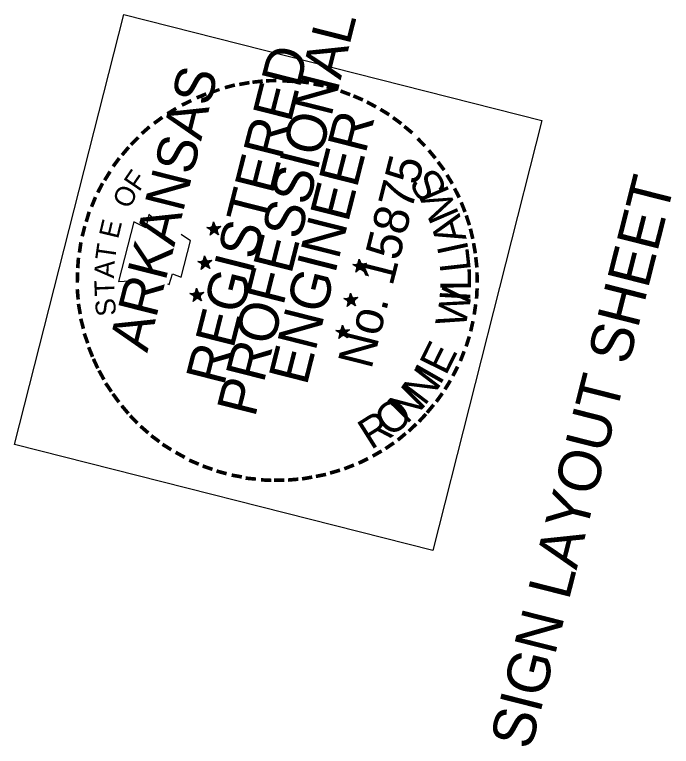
# Model space of a CAD drawing. Extents: x 670257 to 671518, y 737783 to 738188.
# Drawn here: x 670784.83 to 670793.09, y 738048.64 to 738057.85 of the extents above; entities that cross this region are included whole.
import ezdxf

# ---------------------------------------------------------------- set-up
doc = ezdxf.new("R2010")
doc.units = 0
for name, color, linetype in [('R_Border Notes', 7, 'Continuous'), ('R_Border PE', 7, 'Continuous'), ('R_Border Prem', 7, 'Continuous')]:
    doc.layers.add(name, color=color, linetype=linetype)

msp = doc.modelspace()

# ---------------------------------------------------------------- linework, layer by layer
at = {"layer": 'R_Border PE'}
for p, q in [((670787.3344, 738055.24), (670787.3202, 738055.1637)), ((670787.3344, 738055.24), (670787.3287, 738055.1667)), ((670787.3344, 738055.24), (670787.3335, 738055.1654)), ((670787.3344, 738055.24), (670787.3395, 738055.1484)), ((670787.3344, 738055.24), (670787.3427, 738055.1812)), ((670787.3344, 738055.24), (670787.3457, 738055.183)), ((670787.3344, 738055.24), (670787.3494, 738055.1872)), ((670787.2523, 738055.1706), (670787.3172, 738055.1722)), ((670787.3395, 738055.1484), (670787.2523, 738055.1706)), ((670787.2523, 738055.1706), (670787.3159, 738055.1673)), ((670787.2523, 738055.1706), (670787.3117, 738055.1607)), ((670787.2523, 738055.1706), (670787.3116, 738055.1504)), ((670787.2523, 738055.1706), (670787.3104, 738055.1455)), ((670787.2523, 738055.1706), (670787.3068, 738055.1413)), ((670787.2914, 738055.0704), (670787.3395, 738055.1484)), ((670787.4251, 738055.1809), (670787.3395, 738055.1484)), ((670787.3987, 738055.0767), (670787.3395, 738055.1484)), ((670787.4251, 738055.1809), (670787.3469, 738055.1672)), ((670787.4251, 738055.1809), (670787.3481, 738055.1721)), ((670787.4251, 738055.1809), (670787.3559, 738055.1623)), ((670787.4251, 738055.1809), (670787.3589, 738055.1435)), ((670787.4251, 738055.1809), (670787.3638, 738055.1526)), ((670787.4251, 738055.1809), (670787.3662, 738055.1417)), ((670787.2914, 738055.0704), (670787.3146, 738055.1316)), ((670787.2914, 738055.0704), (670787.3188, 738055.1279)), ((670787.2914, 738055.0704), (670787.3213, 738055.1273)), ((670787.2914, 738055.0704), (670787.3303, 738055.1224)), ((670787.2914, 738055.0704), (670787.3352, 738055.1212)), ((670787.2914, 738055.0704), (670787.34, 738055.1199)), ((670787.3987, 738055.0767), (670787.3382, 738055.123)), ((670787.3987, 738055.0767), (670787.3461, 738055.1236)), ((670787.3987, 738055.0767), (670787.3498, 738055.1278)), ((670787.3987, 738055.0767), (670787.3589, 738055.1435)), ((670787.3987, 738055.0767), (670787.3589, 738055.1332)), ((670787.3987, 738055.0767), (670787.3668, 738055.1441)), ((670787.2232, 738054.8117), (670787.209, 738054.7354)), ((670787.2232, 738054.8117), (670787.2175, 738054.7384)), ((670787.2232, 738054.8117), (670787.2223, 738054.7371)), ((670787.2232, 738054.8117), (670787.2283, 738054.7201)), ((670787.2232, 738054.8117), (670787.2315, 738054.7529)), ((670787.2232, 738054.8117), (670787.2351, 738054.7571)), ((670787.2232, 738054.8117), (670787.2382, 738054.7589)), ((670787.1387, 738054.7429), (670787.206, 738054.7439)), ((670787.2283, 738054.7201), (670787.1387, 738054.7429)), ((670787.1387, 738054.7429), (670787.2023, 738054.7396)), ((670787.1387, 738054.7429), (670787.2005, 738054.7324)), ((670787.1387, 738054.7429), (670787.198, 738054.7227)), ((670787.1387, 738054.7429), (670787.1992, 738054.7172)), ((670787.1387, 738054.7429), (670787.1962, 738054.7154)), ((670787.1802, 738054.6421), (670787.2283, 738054.7201)), ((670787.1802, 738054.6421), (670787.201, 738054.7039)), ((670787.1802, 738054.6421), (670787.2058, 738054.7026)), ((670787.1802, 738054.6421), (670787.2101, 738054.699)), ((670787.1802, 738054.6421), (670787.2191, 738054.6941)), ((670787.1802, 738054.6421), (670787.224, 738054.6929)), ((670787.1802, 738054.6421), (670787.2288, 738054.6916)), ((670787.2881, 738054.6508), (670787.227, 738054.6947)), ((670787.3145, 738054.755), (670787.2283, 738054.7201)), ((670787.2881, 738054.6508), (670787.2283, 738054.7201)), ((670787.3145, 738054.755), (670787.2345, 738054.7444)), ((670787.2881, 738054.6508), (670787.2349, 738054.6953)), ((670787.3145, 738054.755), (670787.2357, 738054.7389)), ((670787.2881, 738054.6508), (670787.2386, 738054.6995)), ((670787.3145, 738054.755), (670787.2447, 738054.734)), ((670787.3145, 738054.755), (670787.2477, 738054.7152)), ((670787.2881, 738054.6508), (670787.2477, 738054.7152)), ((670787.2881, 738054.6508), (670787.2477, 738054.7049)), ((670787.3145, 738054.755), (670787.2526, 738054.7243)), ((670787.3145, 738054.755), (670787.255, 738054.7134)), ((670787.2881, 738054.6508), (670787.2556, 738054.7158)), ((670789.1739, 738054.6832), (670789.0867, 738054.7053)), ((670789.0867, 738054.7053), (670789.151, 738054.7045)), ((670789.0867, 738054.7053), (670789.1504, 738054.7021)), ((670789.0867, 738054.7053), (670789.1485, 738054.6948)), ((670789.0867, 738054.7053), (670789.1461, 738054.6851)), ((670789.0867, 738054.7053), (670789.1448, 738054.6803)), ((670789.0867, 738054.7053), (670789.1436, 738054.6754)), ((670789.1682, 738054.7723), (670789.1546, 738054.6984)), ((670789.1682, 738054.7723), (670789.1631, 738054.7014)), ((670789.1682, 738054.7723), (670789.1679, 738054.7002)), ((670789.1682, 738054.7723), (670789.1739, 738054.6832)), ((670789.1682, 738054.7723), (670789.1765, 738054.7135)), ((670789.1682, 738054.7723), (670789.1826, 738054.7171)), ((670789.1682, 738054.7723), (670789.1856, 738054.7189)), ((670789.2596, 738054.7156), (670789.1739, 738054.6832)), ((670789.2596, 738054.7156), (670789.1807, 738054.6995)), ((670789.2596, 738054.7156), (670789.1819, 738054.7044)), ((670789.2596, 738054.7156), (670789.1922, 738054.694)), ((670789.2596, 738054.7156), (670789.1951, 738054.6752)), ((670789.2596, 738054.7156), (670789.1976, 738054.6849)), ((670789.2596, 738054.7156), (670789.2024, 738054.6734)), ((670789.1258, 738054.6051), (670789.1739, 738054.6832)), ((670789.1258, 738054.6051), (670789.1484, 738054.6639)), ((670789.1258, 738054.6051), (670789.1533, 738054.6627)), ((670789.1258, 738054.6051), (670789.1575, 738054.659)), ((670789.1258, 738054.6051), (670789.1648, 738054.6572)), ((670789.1258, 738054.6051), (670789.1714, 738054.6529)), ((670789.1258, 738054.6051), (670789.1763, 738054.6517)), ((670789.2331, 738054.6114), (670789.172, 738054.6553)), ((670789.2331, 738054.6114), (670789.1739, 738054.6832)), ((670789.2331, 738054.6114), (670789.1823, 738054.6553)), ((670789.2331, 738054.6114), (670789.1866, 738054.6619)), ((670789.2331, 738054.6114), (670789.1933, 738054.668)), ((670789.2331, 738054.6114), (670789.1951, 738054.6752)), ((670789.2331, 738054.6114), (670789.2006, 738054.6764)), ((670787.036, 738054.3382), (670787.1033, 738054.3392)), ((670787.1257, 738054.3155), (670787.036, 738054.3382)), ((670787.036, 738054.3382), (670787.0997, 738054.3349)), ((670787.036, 738054.3382), (670787.0984, 738054.3301)), ((670787.036, 738054.3382), (670787.096, 738054.3204)), ((670787.036, 738054.3382), (670787.0966, 738054.3125)), ((670787.036, 738054.3382), (670787.0935, 738054.3107)), ((670787.1205, 738054.407), (670787.1063, 738054.3307)), ((670787.1205, 738054.407), (670787.1148, 738054.3337)), ((670787.1205, 738054.407), (670787.1197, 738054.3325)), ((670787.1205, 738054.407), (670787.1257, 738054.3155)), ((670787.1205, 738054.407), (670787.1288, 738054.3482)), ((670787.1205, 738054.407), (670787.1325, 738054.3524)), ((670787.1205, 738054.407), (670787.1355, 738054.3542)), ((670787.2119, 738054.3503), (670787.1257, 738054.3155)), ((670787.2119, 738054.3503), (670787.1318, 738054.3397)), ((670787.2119, 738054.3503), (670787.133, 738054.3342)), ((670787.2119, 738054.3503), (670787.1421, 738054.3293)), ((670787.2119, 738054.3503), (670787.1451, 738054.3105)), ((670787.2119, 738054.3503), (670787.1499, 738054.3196)), ((670787.2119, 738054.3503), (670787.1523, 738054.3087)), ((670789.057, 738054.344), (670789.0434, 738054.2701)), ((670789.057, 738054.344), (670789.0519, 738054.2731)), ((670789.057, 738054.344), (670789.0567, 738054.2719)), ((670789.057, 738054.344), (670789.0627, 738054.2549)), ((670789.057, 738054.344), (670789.0653, 738054.2852)), ((670789.057, 738054.344), (670789.0689, 738054.2894)), ((670789.057, 738054.344), (670789.075, 738054.2931)), ((670787.0775, 738054.2374), (670787.1257, 738054.3155)), ((670787.0775, 738054.2374), (670787.0983, 738054.2992)), ((670787.0775, 738054.2374), (670787.1032, 738054.2979)), ((670787.0775, 738054.2374), (670787.1074, 738054.2943)), ((670787.0775, 738054.2374), (670787.1171, 738054.2918)), ((670787.0775, 738054.2374), (670787.1213, 738054.2882)), ((670787.0775, 738054.2374), (670787.1262, 738054.287)), ((670787.1855, 738054.2461), (670787.1244, 738054.29)), ((670787.1855, 738054.2461), (670787.1257, 738054.3155)), ((670787.1855, 738054.2461), (670787.1323, 738054.2906)), ((670787.1855, 738054.2461), (670787.1359, 738054.2948)), ((670787.1855, 738054.2461), (670787.145, 738054.3002)), ((670787.1855, 738054.2461), (670787.1451, 738054.3105)), ((670787.1855, 738054.2461), (670787.153, 738054.3111)), ((670789.0627, 738054.2549), (670788.9755, 738054.277)), ((670788.9755, 738054.277), (670789.0398, 738054.2762)), ((670788.9755, 738054.277), (670789.0392, 738054.2738)), ((670788.9755, 738054.277), (670789.0373, 738054.2665)), ((670788.9755, 738054.277), (670789.0349, 738054.2568)), ((670788.9755, 738054.277), (670789.0336, 738054.252)), ((670788.9755, 738054.277), (670789.03, 738054.2477)), ((670789.0146, 738054.1768), (670789.0627, 738054.2549)), ((670789.0146, 738054.1768), (670789.0372, 738054.2356)), ((670789.0146, 738054.1768), (670789.0421, 738054.2343)), ((670789.0146, 738054.1768), (670789.0445, 738054.2337)), ((670789.0146, 738054.1768), (670789.0536, 738054.2289)), ((670789.0146, 738054.1768), (670789.0584, 738054.2276)), ((670789.0146, 738054.1768), (670789.0632, 738054.2264)), ((670789.1219, 738054.1831), (670789.0614, 738054.2294)), ((670789.1483, 738054.2873), (670789.0627, 738054.2549)), ((670789.1219, 738054.1831), (670789.0627, 738054.2549)), ((670789.1483, 738054.2873), (670789.0695, 738054.2712)), ((670789.1483, 738054.2873), (670789.0713, 738054.2785)), ((670789.1219, 738054.1831), (670789.0717, 738054.2294)), ((670789.1219, 738054.1831), (670789.0754, 738054.2336)), ((670789.1483, 738054.2873), (670789.0792, 738054.2688)), ((670789.1219, 738054.1831), (670789.0821, 738054.25)), ((670789.1219, 738054.1831), (670789.0821, 738054.2397)), ((670789.1483, 738054.2873), (670789.0845, 738054.2494)), ((670789.1483, 738054.2873), (670789.0864, 738054.2566)), ((670789.1483, 738054.2873), (670789.0888, 738054.2457)), ((670789.1219, 738054.1831), (670789.0894, 738054.2481)), ((670788.8729, 738053.8723), (670788.9377, 738053.8739)), ((670788.9601, 738053.8502), (670788.8729, 738053.8723)), ((670788.8729, 738053.8723), (670788.9365, 738053.8691)), ((670788.8729, 738053.8723), (670788.9347, 738053.8618)), ((670788.8729, 738053.8723), (670788.9322, 738053.8521)), ((670788.8729, 738053.8723), (670788.931, 738053.8473)), ((670788.8729, 738053.8723), (670788.9273, 738053.843)), ((670788.955, 738053.9418), (670788.9407, 738053.8654)), ((670788.955, 738053.9418), (670788.9492, 738053.8684)), ((670788.955, 738053.9418), (670788.9541, 738053.8672)), ((670788.955, 738053.9418), (670788.9601, 738053.8502)), ((670788.955, 738053.9418), (670788.9626, 738053.8805)), ((670788.955, 738053.9418), (670788.9663, 738053.8847)), ((670788.955, 738053.9418), (670788.9724, 738053.8884)), ((670789.0457, 738053.8827), (670788.9601, 738053.8502)), ((670789.0457, 738053.8827), (670788.9668, 738053.8666)), ((670789.0457, 738053.8827), (670788.9687, 738053.8738)), ((670789.0457, 738053.8827), (670788.9765, 738053.8641)), ((670789.0457, 738053.8827), (670788.9819, 738053.8447)), ((670789.0457, 738053.8827), (670788.9838, 738053.8519)), ((670789.0457, 738053.8827), (670788.9861, 738053.841)), ((670788.9119, 738053.7722), (670788.9601, 738053.8502)), ((670788.9119, 738053.7722), (670788.9352, 738053.8333)), ((670788.9119, 738053.7722), (670788.9394, 738053.8297)), ((670788.9119, 738053.7722), (670788.9418, 738053.829)), ((670788.9119, 738053.7722), (670788.9509, 738053.8242)), ((670788.9119, 738053.7722), (670788.9558, 738053.8229)), ((670788.9119, 738053.7722), (670788.9606, 738053.8217)), ((670789.0193, 738053.7785), (670788.9588, 738053.8247)), ((670789.0193, 738053.7785), (670788.9601, 738053.8502)), ((670789.0193, 738053.7785), (670788.9691, 738053.8247)), ((670789.0193, 738053.7785), (670788.9728, 738053.8289)), ((670789.0193, 738053.7785), (670788.9795, 738053.8453)), ((670789.0193, 738053.7785), (670788.9795, 738053.835)), ((670789.0193, 738053.7785), (670788.9868, 738053.8434))]:
    msp.add_line(p, q, dxfattribs=at)
for points in [[(670786.579, 738055.282), (670786.5198, 738055.3331), (670786.4822, 738055.1647), (670786.3315, 738055.2416), (670786.1404, 738054.488)], [(670787.2523, 738055.1706), (670787.4251, 738055.1809), (670787.2914, 738055.0704), (670787.3344, 738055.24), (670787.3987, 738055.0767), (670787.2523, 738055.1706)], [(670786.7569, 738054.458), (670786.7787, 738054.4525), (670786.818, 738054.5869), (670786.9288, 738054.5459), (670787.0437, 738054.9991), (670786.9276, 738055.0801)], [(670787.1387, 738054.7429), (670787.3145, 738054.755), (670787.1802, 738054.6421), (670787.2232, 738054.8117), (670787.2881, 738054.6508), (670787.1387, 738054.7429)], [(670789.0867, 738054.7053), (670789.2596, 738054.7156), (670789.1258, 738054.6051), (670789.1682, 738054.7723), (670789.2331, 738054.6114), (670789.0867, 738054.7053)], [(670786.1404, 738054.488), (670786.3575, 738054.5)], [(670787.036, 738054.3382), (670787.2119, 738054.3503), (670787.0775, 738054.2374), (670787.1205, 738054.407), (670787.1855, 738054.2461), (670787.036, 738054.3382)], [(670788.9755, 738054.277), (670789.1483, 738054.2873), (670789.0146, 738054.1768), (670789.057, 738054.344), (670789.1219, 738054.1831), (670788.9755, 738054.277)], [(670788.8729, 738053.8723), (670789.0457, 738053.8827), (670788.9119, 738053.7722), (670788.955, 738053.9418), (670789.0193, 738053.7785), (670788.8729, 738053.8723)]]:
    msp.add_lwpolyline(points, dxfattribs=at)
for centre, radius in [((670787.3401, 738055.1481), 0.0431), ((670787.3401, 738055.1481), 0.039), ((670787.3401, 738055.1481), 0.0361), ((670787.3401, 738055.1481), 0.0332), ((670787.3401, 738055.1481), 0.0289), ((670787.3401, 738055.1481), 0.0269), ((670787.3401, 738055.1481), 0.0248), ((670787.3401, 738055.1481), 0.0213), ((670787.3401, 738055.1481), 0.0187), ((670787.3401, 738055.1481), 0.0155), ((670787.3401, 738055.1481), 0.0124), ((670787.3401, 738055.1481), 0.00924), ((670787.3401, 738055.1481), 0.00741), ((670787.3401, 738055.1481), 0.0036), ((670787.2286, 738054.7206), 0.0431), ((670787.2286, 738054.7206), 0.039), ((670787.2286, 738054.7206), 0.0361), ((670787.2286, 738054.7206), 0.0332), ((670787.2286, 738054.7206), 0.0289), ((670787.2286, 738054.7206), 0.0269), ((670787.2286, 738054.7206), 0.0248), ((670787.2286, 738054.7206), 0.0213), ((670787.2286, 738054.7206), 0.0187), ((670787.2286, 738054.7206), 0.0155), ((670787.2286, 738054.7206), 0.0124), ((670787.2286, 738054.7206), 0.00924), ((670787.2286, 738054.7206), 0.00741), ((670787.2286, 738054.7206), 0.0036), ((670789.175, 738054.6817), 0.0431), ((670789.175, 738054.6817), 0.039), ((670789.175, 738054.6817), 0.0361), ((670789.175, 738054.6817), 0.0332), ((670789.175, 738054.6817), 0.0289), ((670789.175, 738054.6817), 0.0269), ((670789.175, 738054.6817), 0.0248), ((670789.175, 738054.6817), 0.0213), ((670789.175, 738054.6817), 0.0187), ((670789.175, 738054.6817), 0.0155), ((670789.175, 738054.6817), 0.0124), ((670789.175, 738054.6817), 0.00924), ((670789.175, 738054.6817), 0.00741), ((670789.175, 738054.6817), 0.0036), ((670787.1261, 738054.3161), 0.0431), ((670787.1261, 738054.3161), 0.039), ((670787.1261, 738054.3161), 0.0361), ((670787.1261, 738054.3161), 0.0332), ((670787.1261, 738054.3161), 0.0289), ((670787.1261, 738054.3161), 0.0269), ((670787.1261, 738054.3161), 0.0248), ((670787.1261, 738054.3161), 0.0213), ((670787.1261, 738054.3161), 0.0187), ((670787.1261, 738054.3161), 0.0155), ((670787.1261, 738054.3161), 0.0124), ((670787.1261, 738054.3161), 0.00924), ((670787.1261, 738054.3161), 0.00741), ((670787.1261, 738054.3161), 0.0036), ((670789.0635, 738054.2542), 0.0431), ((670789.0635, 738054.2542), 0.039), ((670789.0635, 738054.2542), 0.0361), ((670789.0635, 738054.2542), 0.0332), ((670789.0635, 738054.2542), 0.0289), ((670789.0635, 738054.2542), 0.0269), ((670789.0635, 738054.2542), 0.0248), ((670789.0635, 738054.2542), 0.0213), ((670789.0635, 738054.2542), 0.0187), ((670789.0635, 738054.2542), 0.0155), ((670789.0635, 738054.2542), 0.0124), ((670789.0635, 738054.2542), 0.00924), ((670789.0635, 738054.2542), 0.00741), ((670789.0635, 738054.2542), 0.0036), ((670788.961, 738053.8497), 0.0431), ((670788.961, 738053.8497), 0.039), ((670788.961, 738053.8497), 0.0361), ((670788.961, 738053.8497), 0.0332), ((670788.961, 738053.8497), 0.0289), ((670788.961, 738053.8497), 0.0269), ((670788.961, 738053.8497), 0.0248), ((670788.961, 738053.8497), 0.0213), ((670788.961, 738053.8497), 0.0187), ((670788.961, 738053.8497), 0.0155), ((670788.961, 738053.8497), 0.0124), ((670788.961, 738053.8497), 0.00924), ((670788.961, 738053.8497), 0.00741), ((670788.961, 738053.8497), 0.0036)]:
    msp.add_circle(centre, radius, dxfattribs=at)
at = {"layer": 'R_Border Prem'}
msp.add_lwpolyline([(670784.8346, 738052.4383), (670786.2064, 738057.8471), (670791.4647, 738056.5134), (670790.0929, 738051.1047)], close=True, dxfattribs=at)

# ---------------------------------------------------------------- texts
at = {"layer": 'R_Border Notes'}
msp.add_text('SIGN LAYOUT SHEET', height=0.533593, rotation=75.76855, dxfattribs=at).set_placement((670791.3239, 738048.583))
at = {"layer": 'R_Border PE'}
for s, height, rotation, p in [('PROFESSIONAL', 0.499995, 75.76855, (670787.8553, 738052.7686)), ('REGISTERED', 0.5, 75.76855, (670787.4656, 738053.1641)), ('ARKANSAS', 0.5, 75.76855, (670786.5017, 738053.5839)), ('-', 0.3999, 10.43135, (670787.6635, 738056.8124)), ('-', 0.3999, 6.34138, (670787.8176, 738056.8403)), ('-', 0.4, 0.89181, (670787.9723, 738056.8604)), ('-', 0.4, 356.31789, (670788.1664, 738056.8628)), ('-', 0.4, 352.36471, (670788.361, 738056.8573)), ('-', 0.4, 350.09866, (670788.5416, 738056.827)), ('-', 0.35, 19.44384, (670787.3286, 738056.7323)), ('-', 0.4, 15.4369, (670787.496, 738056.7723)), ('-', 0.3999, 345.70922, (670788.6961, 738056.7955)), ('-', 0.3999, 339.28575, (670788.8548, 738056.7501)), ('-', 0.3999, 22.42073, (670787.1603, 738056.6485)), ('-', 0.4, 336.76384, (670789.0104, 738056.6926)), ('-', 0.3999, 25.64828, (670786.983, 738056.5594)), ('-', 0.3999, 331.53115, (670789.1684, 738056.6241)), ('-', 0.4, 31.34714, (670786.8146, 738056.4551)), ('-', 0.4, 328.63664, (670789.3318, 738056.5362)), ('-', 0.4, 36.29826, (670786.659, 738056.3398)), ('ENGINEER', 0.5, 75.76855, (670788.5061, 738053.1684)), ('-', 0.4, 323.65722, (670789.4807, 738056.4418)), ('-', 0.3999, 41.63121, (670786.5173, 738056.2184)), ('-', 0.4, 320.38827, (670789.6168, 738056.3376)), ('-', 0.3999, 45.40945, (670786.3908, 738056.0854)), ('-', 0.4, 314.8398, (670789.7745, 738056.197)), ('-', 0.4, 49.88964, (670786.2873, 738055.9621)), ('No. 15875', 0.44, 75.76855, (670789.3191, 738053.3744)), ('-', 0.4, 309.61379, (670789.9075, 738056.0601)), ('-', 0.4, 53.62364, (670786.1831, 738055.826)), ('-', 0.4, 307.02232, (670790.0192, 738055.9209)), ('-', 0.4, 58.10475, (670786.0843, 738055.6602)), ('F', 0.2499, 55.83921, (670786.3988, 738055.6088)), ('S', 0.3849, 121.46196, (670790.2882, 738055.6493)), ('-', 0.3999, 301.53388, (670790.1254, 738055.7702)), ('-', 0.4, 62.97344, (670786.0068, 738055.5174)), ('O', 0.2499, 66.22005, (670786.2847, 738055.3928)), ('M', 0.3849, 113.32556, (670790.4291, 738055.3335)), ('-', 0.3999, 296.85364, (670790.217, 738055.6128)), ('-', 0.4, 67.93028, (670785.9359, 738055.3497)), ('-', 0.3999, 291.50488, (670790.2971, 738055.4506)), ('-', 0.4, 73.51159, (670785.8759, 738055.1741)), ('A', 0.3849, 105.76014, (670790.5188, 738055.0246)), ('E', 0.25, 76.60089, (670786.1349, 738055.0155)), ('-', 0.4, 288.01764, (670790.3584, 738055.2958)), ('-', 0.3999, 75.95478, (670785.8286, 738054.9978)), ('-', 0.4, 283.12539, (670790.4094, 738055.141)), ('-', 0.3999, 81.66537, (670785.7983, 738054.8069)), ('T', 0.25, 81.79131, (670786.0939, 738054.7422)), ('I', 0.3849, 102.33428, (670790.5458, 738054.8814)), ('-', 0.3999, 280.02017, (670790.4482, 738054.9687)), ('L', 0.3849, 96.33904, (670790.5724, 738054.6279)), ('-', 0.4, 85.9879, (670785.78, 738054.6232)), ('-', 0.4, 276.48697, (670790.4756, 738054.8019)), ('A', 0.25, 86.98173, (670786.0829, 738054.5258)), ('-', 0.3999, 89.3987, (670785.777, 738054.4486)), ('L', 0.3849, 90.3438, (670790.5724, 738054.3729)), ('-', 0.3999, 271.24284, (670790.4925, 738054.6247)), ('T', 0.2499, 92.17215, (670786.0925, 738054.3093)), ('W', 0.3849, 78.78155, (670790.4973, 738053.8877)), ('-', 0.3999, 94.94463, (670785.7891, 738054.2521)), ('I', 0.3849, 86.91795, (670790.5604, 738054.2277)), ('-', 0.4, 267.05431, (670790.4961, 738054.4355)), ('S', 0.2499, 97.36257, (670786.1165, 738054.0685)), ('-', 0.4, 100.07576, (670785.8158, 738054.0828)), ('-', 0.3999, 261.58522, (670790.4822, 738054.2482)), ('-', 0.4, 104.56037, (670785.8546, 738053.9105)), ('-', 0.4, 257.36031, (670790.4518, 738054.047)), ('-', 0.4, 109.83212, (670785.9074, 738053.7424)), ('-', 0.4, 252.28682, (670790.4111, 738053.8665)), ('-', 0.3999, 112.00029, (670785.9663, 738053.5778)), ('E', 0.3849, 63.72208, (670790.257, 738053.2958)), ('-', 0.4, 248.88401, (670790.3505, 738053.6884)), ('-', 0.3999, 114.71921, (670786.0295, 738053.4406)), ('N', 0.3849, 52.7308, (670789.9884, 738052.9139)), ('I', 0.3849, 60.29623, (670790.1812, 738053.1713)), ('-', 0.4, 243.32407, (670790.2765, 738053.5086)), ('-', 0.3999, 118.7308, (670786.1042, 738053.3082)), ('-', 0.4, 124.1916, (670786.1929, 738053.1696)), ('-', 0.4, 238.56682, (670790.1935, 738053.344)), ('N', 0.3849, 45.16538, (670789.7634, 738052.6842)), ('-', 0.3999, 126.38273, (670786.2846, 738053.0432)), ('-', 0.4, 234.32977, (670790.1008, 738053.1921)), ('-', 0.4, 130.00102, (670786.3975, 738052.9088)), ('O', 0.3849, 38.88465, (670789.5549, 738052.5173)), ('-', 0.3999, 230.36875, (670789.9991, 738053.0554)), ('-', 0.4, 133.83918, (670786.5057, 738052.7963)), ('R', 0.3849, 32.17569, (670789.3135, 738052.3654)), ('-', 0.3999, 227.33894, (670789.909, 738052.9441)), ('-', 0.3999, 138.6399, (670786.6344, 738052.6836)), ('-', 0.4, 223.85834, (670789.7934, 738052.8239)), ('-', 0.3999, 143.54282, (670786.7663, 738052.5831)), ('-', 0.3999, 220.41489, (670789.6693, 738052.7109)), ('-', 0.4, 214.70237, (670789.5355, 738052.6004)), ('-', 0.3999, 148.16302, (670786.9054, 738052.4911)), ('-', 0.4, 151.22951, (670787.0682, 738052.4008)), ('-', 0.4, 209.99236, (670789.3921, 738052.5027)), ('-', 0.3999, 156.96982, (670787.2317, 738052.3233)), ('-', 0.4, 201.662, (670789.0653, 738052.3328)), ('-', 0.3999, 206.48667, (670789.2293, 738052.4098)), ('-', 0.3999, 160.95489, (670787.3946, 738052.2639)), ('-', 0.4, 164.83079, (670787.5624, 738052.2136)), ('-', 0.4, 196.21567, (670788.905, 738052.2703)), ('-', 0.3999, 169.96443, (670787.7417, 738052.1784)), ('-', 0.3999, 174.71648, (670787.906, 738052.1548)), ('-', 0.4, 177.4835, (670788.0933, 738052.1408)), ('-', 0.3999, 184.85597, (670788.4123, 738052.158)), ('-', 0.3999, 189.83287, (670788.5736, 738052.1841)), ('-', 0.3999, 191.4974, (670788.7423, 738052.2187)), ('-', 0.4, 181.2264, (670788.2467, 738052.1458))]:
    msp.add_text(s, height=height, rotation=rotation, dxfattribs=at).set_placement(p)

doc.saveas('drawing.dxf')
